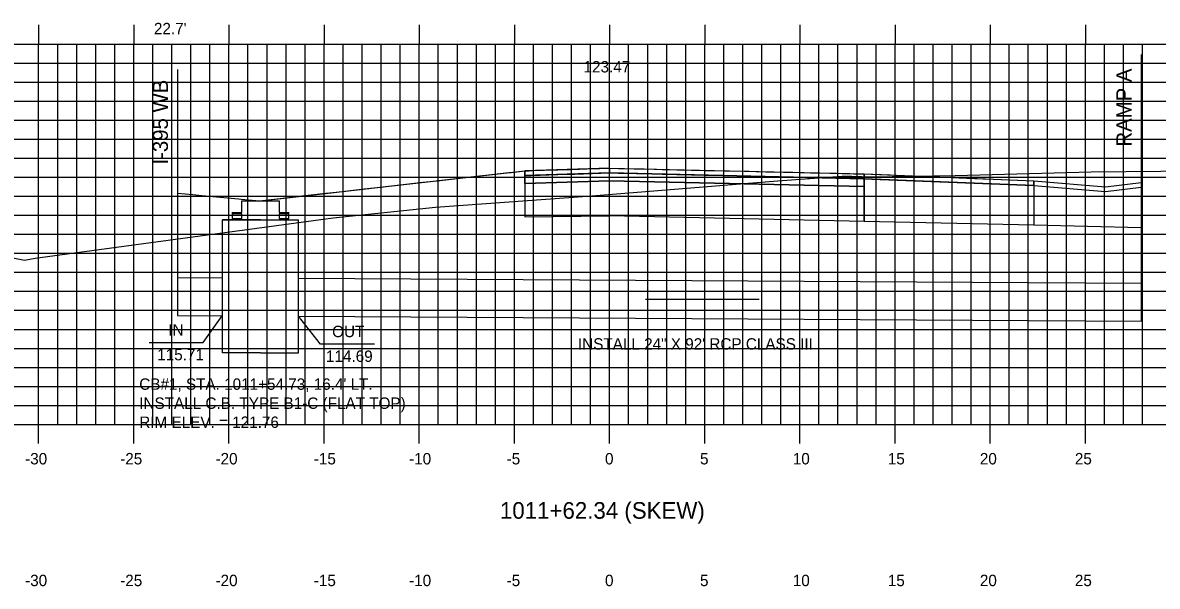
# Model space of a CAD drawing. Extents: x 852404 to 852575, y 365624 to 365734.
# Drawn here: x 852456 to 852515.6, y 365654.5 to 365684.1 of the extents above; entities that cross this region are included whole.
import ezdxf

# ---------------------------------------------------------------- set-up
doc = ezdxf.new("R2010")
doc.units = 0
for name, color, linetype in [('ANNOTATION', 7, 'Continuous'), ('D_Drainage_CB_TypeA1-B1', 7, 'Continuous'), ('D_Drainage_Culvert', 7, 'Continuous'), ('D_Drainage_Text', 7, 'Continuous'), ('D_Roadway_Centerline', 7, 'Continuous'), ('D_Roadway_Centerline_Text', 7, 'Continuous'), ('D_Roadway_Edge_Shoulder', 7, 'Continuous'), ('D_Roadway_Edge_TW', 7, 'Continuous'), ('D_Roadway_FinishedGrade', 7, 'Continuous'), ('D_Roadway_Pavement', 7, 'Continuous'), ('D_Roadway_SubGrade', 7, 'Continuous'), ('D_Text_Standard', 7, 'Continuous'), ('H_V ANNOTATION', 7, 'Continuous'), ('MAJOR', 7, 'Continuous'), ('MINOR', 7, 'Continuous'), ('S_Roadway_Centerline', 7, 'Continuous')]:
    doc.layers.add(name, color=color, linetype=linetype)

msp = doc.modelspace()

# ---------------------------------------------------------------- linework, layer by layer
at = {"layer": 'ANNOTATION'}
for points in [[(852462.592, 365667.335), (852465.438, 365667.335), (852466.434, 365668.741)], [(852474.44, 365667.253), (852471.594, 365667.253), (852470.446, 365668.718)]]:
    msp.add_lwpolyline(points, dxfattribs=at)
at = {"layer": 'D_Drainage_CB_TypeA1-B1'}
for p, q in [((852468.446, 365673.787), (852466.446, 365673.787)), ((852466.446, 365673.787), (852470.446, 365673.787))]:
    msp.add_line(p, q, dxfattribs=at)
for points in [[(852466.936, 365674.164), (852467.461, 365674.164), (852467.461, 365674.787), (852469.43, 365674.787), (852469.43, 365674.164), (852469.955, 365674.164)], [(852468.446, 365666.787), (852466.446, 365666.787), (852466.446, 365673.787)], [(852468.446, 365666.787), (852470.446, 365666.787), (852470.446, 365673.787)]]:
    msp.add_lwpolyline(points, dxfattribs=at)
for points in [[(852466.961, 365674.101), (852466.961, 365673.851), (852467.461, 365673.851), (852467.461, 365674.101)], [(852469.43, 365674.101), (852469.43, 365673.851), (852469.93, 365673.851), (852469.93, 365674.101)]]:
    msp.add_lwpolyline(points, close=True, dxfattribs=at)
at = {"layer": 'D_Drainage_Culvert'}
for p, q in [((852488.682, 365669.608), (852494.651, 365669.608)), ((852464.093, 365668.755), (852466.434, 365668.741))]:
    msp.add_line(p, q, dxfattribs=at)
for points in [[(852464.093, 365670.755), (852466.446, 365670.741)], [(852470.446, 365670.718), (852514.725, 365670.463)], [(852470.446, 365668.718), (852514.725, 365668.463)]]:
    msp.add_lwpolyline(points, dxfattribs=at)
at = {"layer": 'D_Roadway_Centerline'}
msp.add_line((852514.725, 365675.753), (852514.725, 365673.368), dxfattribs=at)
for points in [[(852468.394, 365674.786), (852469.938, 365674.961), (852470.186, 365674.989), (852471.888, 365675.183), (852472.45, 365675.246), (852473.836, 365675.404), (852474.714, 365675.502), (852475.784, 365675.623), (852476.977, 365675.758), (852477.73, 365675.843), (852479.24, 365676.012), (852479.676, 365676.062), (852481.505, 365676.267), (852481.621, 365676.28), (852482.333, 365676.36), (852483.767, 365676.404), (852484.785, 365676.436), (852486.03, 365676.475), (852486.287, 365676.484), (852486.792, 365676.499), (852488.077, 365676.471), (852488.294, 365676.466), (852488.6, 365676.459), (852490.557, 365676.414), (852491.948, 365676.383), (852492.821, 365676.364), (852493.884, 365676.339), (852495.085, 365676.312), (852496.773, 365676.274), (852497.347, 365676.261), (852497.755, 365676.252), (852499.611, 365676.21), (852499.691, 365676.208), (852500.168, 365676.197), (852501.529, 365676.142), (852501.875, 365676.129), (852502.455, 365676.105), (852504.137, 365676.036), (852505.139, 365675.996), (852506.401, 365675.945), (852506.945, 365675.923), (852508.665, 365675.853), (852509.086, 365675.836)], [(852468.394, 365674.786), (852482.333, 365676.36)], [(852468.394, 365674.786), (852482.333, 365676.36)], [(852468.446, 365674.787), (852471.705, 365675.158), (852472.311, 365675.227), (852473.897, 365675.407), (852474.912, 365675.522), (852476.088, 365675.655), (852477.515, 365675.816), (852478.28, 365675.903), (852480.119, 365676.11), (852480.471, 365676.15), (852482.333, 365676.36), (852482.56, 365676.367), (852482.678, 365676.371), (852484.072, 365676.414), (852484.968, 365676.443), (852486.779, 365676.499), (852487.258, 365676.489), (852489.142, 365676.446), (852489.548, 365676.437), (852491.097, 365676.402), (852491.838, 365676.385), (852493.051, 365676.358), (852494.128, 365676.334), (852495.006, 365676.314), (852496.418, 365676.282), (852496.96, 365676.27), (852498.708, 365676.23), (852500.119, 365676.198), (852509.085, 365675.836), (852512.846, 365675.519), (852514.725, 365675.753)], [(852482.333, 365676.11), (852482.56, 365676.117), (852482.678, 365676.121), (852484.072, 365676.164), (852484.968, 365676.193), (852486.779, 365676.249), (852487.258, 365676.239), (852489.142, 365676.196), (852489.548, 365676.187), (852491.097, 365676.152), (852491.838, 365676.135), (852493.051, 365676.108), (852494.128, 365676.084), (852495.006, 365676.064), (852496.418, 365676.032), (852496.96, 365676.02), (852498.708, 365675.98), (852500.119, 365675.948), (852509.085, 365675.586), (852512.846, 365675.269), (852514.725, 365675.503)], [(852464.093, 365675.187), (852464.899, 365675.112), (852465.361, 365675.068), (852467.289, 365674.889), (852467.435, 365674.875), (852468.395, 365674.786)], [(852514.725, 365673.368), (852509.085, 365673.496)]]:
    msp.add_lwpolyline(points, dxfattribs=at)
at = {"layer": 'D_Roadway_Edge_Shoulder'}
for points in [[(852486.792, 365676.499), (852482.333, 365676.36), (852482.333, 365676.11), (852486.792, 365676.249)], [(852500.168, 365676.197), (852509.085, 365675.836), (852509.085, 365675.586), (852500.168, 365675.947)]]:
    msp.add_lwpolyline(points, close=True, dxfattribs=at)
at = {"layer": 'D_Roadway_Edge_TW'}
msp.add_lwpolyline([(852486.792, 365676.499), (852500.168, 365676.197), (852500.168, 365675.947), (852486.792, 365676.249)], close=True, dxfattribs=at)
msp.add_lwpolyline([(852500.168, 365676.197), (852500.168, 365676.031)], dxfattribs=at)
at = {"layer": 'D_Roadway_FinishedGrade'}
for p, q in [((852482.333, 365676.36), (852482.333, 365676.11)), ((852486.792, 365676.499), (852486.792, 365676.249)), ((852500.168, 365676.197), (852500.168, 365675.947)), ((852509.085, 365675.836), (852509.085, 365675.586))]:
    msp.add_line(p, q, dxfattribs=at)
at = {"layer": 'D_Roadway_Pavement'}
for points in [[(852486.792, 365676.249), (852482.333, 365676.11), (852482.333, 365675.693), (852486.792, 365675.832)], [(852486.792, 365676.249), (852500.168, 365675.947), (852500.168, 365675.531), (852486.792, 365675.832)]]:
    msp.add_lwpolyline(points, close=True, dxfattribs=at)
msp.add_lwpolyline([(852500.168, 365676.031), (852500.168, 365675.531)], dxfattribs=at)
msp.add_lwpolyline([(852500.168, 365676.031), (852500.168, 365675.531)], dxfattribs=at)
at = {"layer": 'D_Roadway_SubGrade'}
for p, q in [((852514.725, 365682.477), (852514.725, 365673.368)), ((852464.093, 365681.68), (852464.093, 365668.755)), ((852514.725, 365673.368), (852514.725, 365668.463))]:
    msp.add_line(p, q, dxfattribs=at)
for points in [[(852486.792, 365675.832), (852482.333, 365675.693), (852482.333, 365676.193), (852482.333, 365676.36), (852482.333, 365673.94), (852486.792, 365673.999)], [(852486.792, 365675.832), (852500.168, 365675.531), (852500.168, 365673.697), (852486.792, 365673.999)], [(852500.168, 365675.531), (852500.168, 365675.947), (852509.085, 365675.586), (852509.085, 365675.836), (852509.085, 365673.496), (852500.168, 365673.697)]]:
    msp.add_lwpolyline(points, close=True, dxfattribs=at)
msp.add_lwpolyline([(852500.168, 365675.531), (852500.168, 365673.697)], dxfattribs=at)
at = {"layer": 'MAJOR'}
for p, q in [((852456.792, 365684.029), (852456.792, 365683.027)), ((852461.792, 365684.029), (852461.792, 365683.027)), ((852466.792, 365684.029), (852466.792, 365683.027)), ((852471.792, 365684.029), (852471.792, 365683.027)), ((852476.792, 365684.029), (852476.792, 365683.027)), ((852481.792, 365684.029), (852481.792, 365683.027)), ((852486.792, 365684.029), (852486.792, 365683.027)), ((852491.792, 365684.029), (852491.792, 365683.027)), ((852496.792, 365684.029), (852496.792, 365683.027)), ((852501.792, 365684.029), (852501.792, 365683.027)), ((852506.792, 365684.029), (852506.792, 365683.027)), ((852511.792, 365684.029), (852511.792, 365683.027)), ((852416.792, 365683.027), (852556.792, 365683.027)), ((852416.792, 365683.027), (852556.792, 365683.027)), ((852456.792, 365663.027), (852456.792, 365683.027)), ((852461.792, 365663.027), (852461.792, 365683.027)), ((852466.792, 365663.027), (852466.792, 365683.027)), ((852471.792, 365663.027), (852471.792, 365683.027)), ((852476.792, 365663.027), (852476.792, 365683.027)), ((852481.792, 365663.027), (852481.792, 365683.027)), ((852486.792, 365663.027), (852486.792, 365683.027)), ((852491.792, 365663.027), (852491.792, 365683.027)), ((852496.792, 365663.027), (852496.792, 365683.027)), ((852501.792, 365663.027), (852501.792, 365683.027)), ((852506.792, 365663.027), (852506.792, 365683.027)), ((852511.792, 365663.027), (852511.792, 365683.027)), ((852416.792, 365678.027), (852556.792, 365678.027)), ((852416.792, 365673.027), (852556.792, 365673.027)), ((852416.792, 365668.027), (852556.792, 365668.027)), ((852416.792, 365663.027), (852556.792, 365663.027)), ((852416.792, 365663.027), (852556.792, 365663.027)), ((852456.792, 365662.025), (852456.792, 365663.027)), ((852461.792, 365662.025), (852461.792, 365663.027)), ((852466.792, 365662.025), (852466.792, 365663.027)), ((852471.792, 365662.025), (852471.792, 365663.027)), ((852476.792, 365662.025), (852476.792, 365663.027)), ((852481.792, 365662.025), (852481.792, 365663.027)), ((852486.792, 365662.025), (852486.792, 365663.027)), ((852491.792, 365662.025), (852491.792, 365663.027)), ((852496.792, 365662.025), (852496.792, 365663.027)), ((852501.792, 365662.025), (852501.792, 365663.027)), ((852506.792, 365662.025), (852506.792, 365663.027)), ((852511.792, 365662.025), (852511.792, 365663.027))]:
    msp.add_line(p, q, dxfattribs=at)
at = {"layer": 'MINOR'}
for p, q in [((852457.792, 365663.027), (852457.792, 365683.027)), ((852458.792, 365663.027), (852458.792, 365683.027)), ((852459.792, 365663.027), (852459.792, 365683.027)), ((852460.792, 365663.027), (852460.792, 365683.027)), ((852462.792, 365663.027), (852462.792, 365683.027)), ((852463.792, 365663.027), (852463.792, 365683.027)), ((852464.792, 365663.027), (852464.792, 365683.027)), ((852465.792, 365663.027), (852465.792, 365683.027)), ((852467.792, 365663.027), (852467.792, 365683.027)), ((852468.792, 365663.027), (852468.792, 365683.027)), ((852469.792, 365663.027), (852469.792, 365683.027)), ((852470.792, 365663.027), (852470.792, 365683.027)), ((852472.792, 365663.027), (852472.792, 365683.027)), ((852473.792, 365663.027), (852473.792, 365683.027)), ((852474.792, 365663.027), (852474.792, 365683.027)), ((852475.792, 365663.027), (852475.792, 365683.027)), ((852477.792, 365663.027), (852477.792, 365683.027)), ((852478.792, 365663.027), (852478.792, 365683.027)), ((852479.792, 365663.027), (852479.792, 365683.027)), ((852480.792, 365663.027), (852480.792, 365683.027)), ((852482.792, 365663.027), (852482.792, 365683.027)), ((852483.792, 365663.027), (852483.792, 365683.027)), ((852484.792, 365663.027), (852484.792, 365683.027)), ((852485.792, 365663.027), (852485.792, 365683.027)), ((852487.792, 365663.027), (852487.792, 365683.027)), ((852488.792, 365663.027), (852488.792, 365683.027)), ((852489.792, 365663.027), (852489.792, 365683.027)), ((852490.792, 365663.027), (852490.792, 365683.027)), ((852492.792, 365663.027), (852492.792, 365683.027)), ((852493.792, 365663.027), (852493.792, 365683.027)), ((852494.792, 365663.027), (852494.792, 365683.027)), ((852495.792, 365663.027), (852495.792, 365683.027)), ((852497.792, 365663.027), (852497.792, 365683.027)), ((852498.792, 365663.027), (852498.792, 365683.027)), ((852499.792, 365663.027), (852499.792, 365683.027)), ((852500.792, 365663.027), (852500.792, 365683.027)), ((852502.792, 365663.027), (852502.792, 365683.027)), ((852503.792, 365663.027), (852503.792, 365683.027)), ((852504.792, 365663.027), (852504.792, 365683.027)), ((852505.792, 365663.027), (852505.792, 365683.027)), ((852507.792, 365663.027), (852507.792, 365683.027)), ((852508.792, 365663.027), (852508.792, 365683.027)), ((852509.792, 365663.027), (852509.792, 365683.027)), ((852510.792, 365663.027), (852510.792, 365683.027)), ((852512.792, 365663.027), (852512.792, 365683.027)), ((852513.792, 365663.027), (852513.792, 365683.027)), ((852514.792, 365663.027), (852514.792, 365683.027)), ((852416.792, 365682.027), (852556.792, 365682.027)), ((852416.792, 365681.027), (852556.792, 365681.027)), ((852416.792, 365680.027), (852556.792, 365680.027)), ((852416.792, 365679.027), (852556.792, 365679.027)), ((852416.792, 365677.027), (852556.792, 365677.027)), ((852416.792, 365676.027), (852556.792, 365676.027)), ((852416.792, 365675.027), (852556.792, 365675.027)), ((852416.792, 365674.027), (852556.792, 365674.027)), ((852416.792, 365672.027), (852556.792, 365672.027)), ((852416.792, 365671.027), (852556.792, 365671.027)), ((852416.792, 365670.027), (852556.792, 365670.027)), ((852416.792, 365669.027), (852556.792, 365669.027)), ((852416.792, 365667.027), (852556.792, 365667.027)), ((852416.792, 365666.027), (852556.792, 365666.027)), ((852416.792, 365665.027), (852556.792, 365665.027)), ((852416.792, 365664.027), (852556.792, 365664.027))]:
    msp.add_line(p, q, dxfattribs=at)
at = {"layer": 'S_Roadway_Centerline'}
msp.add_lwpolyline([(852416.792, 365676.717), (852421.312, 365676.563), (852426.727, 365676.393), (852427.136, 365676.37), (852440.878, 365674.647), (852441.286, 365674.607), (852443.18, 365674.28), (852452.142, 365672.43), (852456.052, 365671.664), (852456.612, 365671.762), (852472.267, 365673.886), (852477.652, 365674.452), (852485.85, 365675.048), (852495.615, 365675.827), (852499.005, 365676.078), (852499.526, 365676.074), (852500.531, 365676.052), (852504.956, 365676.121), (852512.087, 365676.312), (852519.423, 365676.382)], dxfattribs=at)

# ---------------------------------------------------------------- texts
at = {"layer": 'ANNOTATION'}
for s, p in [('RAMP A', (852514.218, 365677.634)), ('I-395 WB', (852463.586, 365676.69))]:
    msp.add_text(s, height=0.8, rotation=90, dxfattribs=at).set_placement(p)
for s, p in [('IN', (852463.605, 365667.698)), ('OUT', (852472.215, 365667.616)), ('115.71', (852463.021, 365666.398)), ('114.69', (852471.889, 365666.316)), ("CB#1, STA. 1011+54.73, 16.4' LT. ", (852462.079, 365664.849)), ('INSTALL C.B. TYPE B1-C (FLAT TOP)', (852462.079, 365663.847)), ('RIM ELEV. = 121.76', (852462.079, 365662.845))]:
    msp.add_text(s, height=0.6, dxfattribs=at).set_placement(p)
at = {"layer": 'D_Drainage_Text'}
msp.add_text('INSTALL 24" X 92\' RCP CLASS III', height=0.6, dxfattribs=at).set_placement((852485.129, 365666.961))
at = {"layer": 'D_Roadway_Centerline_Text'}
msp.add_text('123.47', height=0.6, dxfattribs=at).set_placement((852485.422, 365681.531))
at = {"layer": 'D_Text_Standard'}
msp.add_text("22.7'", height=0.6, dxfattribs=at).set_placement((852462.849, 365683.539))
at = {"layer": 'H_V ANNOTATION'}
for s, height, p in [('-30', 0.6, (852456.08, 365660.927)), ('-25', 0.6, (852461.077, 365660.927)), ('-20', 0.6, (852466.085, 365660.927)), ('-15', 0.6, (852471.249, 365660.927)), ('-10', 0.6, (852476.257, 365660.927)), ('-5', 0.6, (852481.382, 365660.927)), ('0', 0.6, (852486.551, 365660.927)), ('5', 0.6, (852491.543, 365660.927)), ('10', 0.6, (852496.417, 365660.927)), ('15', 0.6, (852501.409, 365660.927)), ('20', 0.6, (852506.246, 365660.927)), ('25', 0.6, (852511.238, 365660.927)), ('1011+62.34 (SKEW)', 0.87498, (852481.029, 365658.07)), ('-30', 0.6, (852456.08, 365654.527)), ('-25', 0.6, (852461.077, 365654.527)), ('-20', 0.6, (852466.085, 365654.527)), ('-15', 0.6, (852471.249, 365654.527)), ('-10', 0.6, (852476.257, 365654.527)), ('-5', 0.6, (852481.382, 365654.527)), ('0', 0.6, (852486.551, 365654.527)), ('5', 0.6, (852491.543, 365654.527)), ('10', 0.6, (852496.417, 365654.527)), ('15', 0.6, (852501.409, 365654.527)), ('20', 0.6, (852506.246, 365654.527)), ('25', 0.6, (852511.238, 365654.527))]:
    msp.add_text(s, height=height, dxfattribs=at).set_placement(p)

doc.saveas('drawing.dxf')
